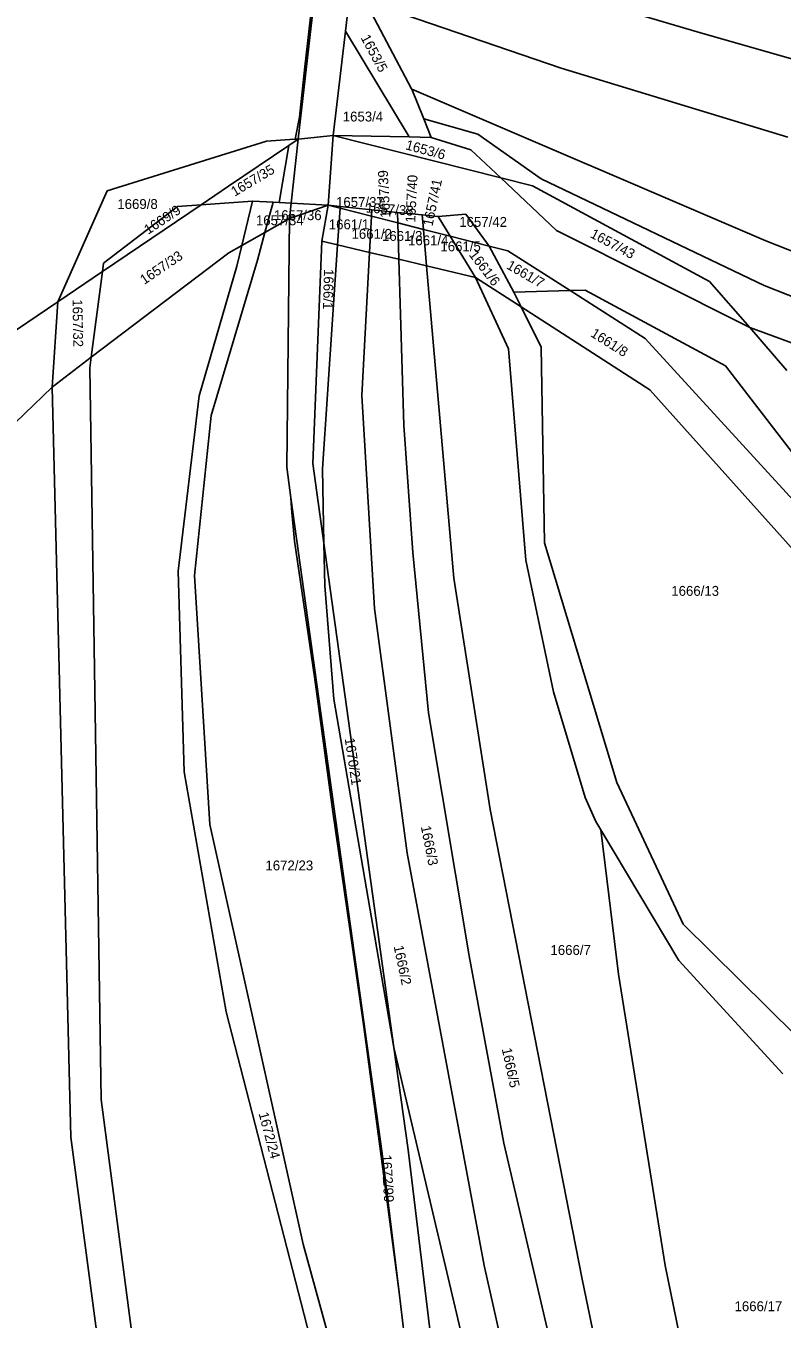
# Model space of a CAD drawing. Extents: x -563148 to -561712, y -1182311 to -1179502.
# Drawn here: x -562402.8 to -562287.9, y -1181888.8 to -1181692.5 of the extents above; entities that cross this region are included whole.
import ezdxf

# ---------------------------------------------------------------- set-up
doc = ezdxf.new("R2010")
doc.units = 0
for name, color, linetype in [('Vrstva 55', 7, 'Continuous'), ('Vrstva 56', 7, 'Continuous'), ('Vrstva 57', 7, 'Continuous')]:
    doc.layers.add(name, color=color, linetype=linetype)

msp = doc.modelspace()

# ---------------------------------------------------------------- linework, layer by layer
at = {"layer": 'Vrstva 55'}
for p, q in [((-562353.53, -1181639.72), (-562361.42, -1181709.69)), ((-562352.46, -1181678.14), (-562300, -1181693.68)), ((-562359.06, -1181686.55), (-562360.44, -1181698.73)), ((-562354.26, -1181693.32), (-562353.26, -1181684.94)), ((-562351.25, -1181688.74), (-562344.21, -1181702.05)), ((-562351.25, -1181688.74), (-562321.53, -1181698.95)), ((-562356.13, -1181709.15), (-562354.26, -1181693.32)), ((-562354.26, -1181693.32), (-562344.6, -1181709.34)), ((-562300, -1181693.68), (-562248.69, -1181708.34)), ((-562360.44, -1181698.73), (-562361.25, -1181706.38)), ((-562287.09, -1181709.38), (-562321.53, -1181698.95)), ((-562344.21, -1181702.05), (-562344.18, -1181702.13)), ((-562344.18, -1181702.13), (-562342.37, -1181706.61)), ((-562344.18, -1181702.13), (-562290.42, -1181725.11)), ((-562361.25, -1181706.38), (-562361.92, -1181709.72)), ((-562342.37, -1181706.61), (-562341.22, -1181709.47)), ((-562342.37, -1181706.61), (-562334.18, -1181708.95)), ((-562366.23, -1181709.99), (-562390.45, -1181717.55)), ((-562362.72, -1181709.77), (-562366.23, -1181709.99)), ((-562362.87, -1181710.67), (-562361.42, -1181709.69)), ((-562361.92, -1181709.72), (-562362.72, -1181709.77)), ((-562361.42, -1181709.69), (-562361.92, -1181709.72)), ((-562361.42, -1181709.69), (-562356.13, -1181709.15)), ((-562356.13, -1181709.15), (-562344.6, -1181709.34)), ((-562356.13, -1181709.15), (-562330.66, -1181715.59)), ((-562344.6, -1181709.34), (-562341.22, -1181709.47)), ((-562341.22, -1181709.47), (-562335.22, -1181711.3)), ((-562324.54, -1181715.73), (-562334.18, -1181708.95)), ((-562372.02, -1181716.86), (-562362.87, -1181710.67)), ((-562364.32, -1181719.33), (-562362.87, -1181710.67)), ((-562335.22, -1181711.3), (-562330.66, -1181715.59)), ((-562330.66, -1181715.59), (-562325.87, -1181716.8)), ((-562330.66, -1181715.59), (-562322.2, -1181723.55)), ((-562290.68, -1181731.89), (-562324.54, -1181715.73)), ((-562390.45, -1181717.55), (-562397.96, -1181734.41)), ((-562376.15, -1181719.65), (-562372.02, -1181716.86)), ((-562298.96, -1181731.29), (-562325.87, -1181716.8)), ((-562391.15, -1181729.8), (-562376.15, -1181719.65)), ((-562379.77, -1181719.9), (-562390.98, -1181728.5)), ((-562379.77, -1181719.9), (-562376.15, -1181719.65)), ((-562376.15, -1181719.65), (-562368.38, -1181719.12)), ((-562369.99, -1181725.83), (-562368.38, -1181719.12)), ((-562368.38, -1181719.12), (-562368.31, -1181719.12)), ((-562368.31, -1181719.12), (-562365.26, -1181719.28)), ((-562366.5, -1181723.86), (-562365.26, -1181719.28)), ((-562365.26, -1181719.28), (-562364.32, -1181719.33)), ((-562364.32, -1181719.33), (-562362.52, -1181719.42)), ((-562356.88, -1181719.72), (-562362.78, -1181721.75)), ((-562362.52, -1181719.42), (-562356.88, -1181719.72)), ((-562357.84, -1181725.18), (-562356.88, -1181719.72)), ((-562356.88, -1181719.72), (-562355.06, -1181719.91)), ((-562356.88, -1181719.72), (-562355.08, -1181720.18)), ((-562355.08, -1181720.18), (-562355.06, -1181719.91)), ((-562355.06, -1181719.91), (-562350.26, -1181720.41)), ((-562366.5, -1181723.86), (-562362.78, -1181721.75)), ((-562363.17, -1181759.5), (-562362.78, -1181721.75)), ((-562355.45, -1181725.74), (-562355.08, -1181720.18)), ((-562355.08, -1181720.18), (-562350.31, -1181721.39)), ((-562350.61, -1181726.88), (-562350.31, -1181721.39)), ((-562350.31, -1181721.39), (-562350.26, -1181720.41)), ((-562350.31, -1181721.39), (-562346.32, -1181722.41)), ((-562350.26, -1181720.41), (-562346.37, -1181720.81)), ((-562346.37, -1181720.81), (-562346.32, -1181722.41)), ((-562346.37, -1181720.81), (-562342.62, -1181721.2)), ((-562342.62, -1181721.2), (-562342.43, -1181723.4)), ((-562342.62, -1181721.2), (-562340.17, -1181721.46)), ((-562336, -1181721.07), (-562340.17, -1181721.46)), ((-562340.17, -1181721.46), (-562338.34, -1181724.44)), ((-562336, -1181721.07), (-562332.44, -1181725.94)), ((-562369.99, -1181725.83), (-562366.5, -1181723.86)), ((-562367.64, -1181728.05), (-562366.5, -1181723.86)), ((-562346.32, -1181722.41), (-562346.15, -1181727.94)), ((-562346.32, -1181722.41), (-562342.43, -1181723.4)), ((-562342.43, -1181723.4), (-562341.95, -1181728.93)), ((-562342.43, -1181723.4), (-562338.34, -1181724.44)), ((-562322.2, -1181723.55), (-562292.88, -1181738.3)), ((-562371.95, -1181726.94), (-562369.99, -1181725.83)), ((-562370.75, -1181728.97), (-562369.99, -1181725.83)), ((-562359.21, -1181758.95), (-562357.84, -1181725.18)), ((-562357.84, -1181725.18), (-562355.45, -1181725.74)), ((-562357.75, -1181759.73), (-562355.45, -1181725.74)), ((-562355.45, -1181725.74), (-562350.61, -1181726.88)), ((-562338.34, -1181724.44), (-562334.52, -1181730.68)), ((-562338.34, -1181724.44), (-562332.44, -1181725.94)), ((-562251.08, -1181740.75), (-562290.42, -1181725.11)), ((-562392.85, -1181742.79), (-562371.95, -1181726.94)), ((-562351.79, -1181748.62), (-562350.61, -1181726.88)), ((-562350.61, -1181726.88), (-562346.15, -1181727.94)), ((-562332.44, -1181725.94), (-562328.71, -1181732.93)), ((-562332.44, -1181725.94), (-562329.62, -1181726.66)), ((-562329.62, -1181726.66), (-562320.13, -1181732.69)), ((-562397.96, -1181734.41), (-562391.15, -1181729.8)), ((-562392.85, -1181742.79), (-562391.15, -1181729.8)), ((-562391.15, -1181729.8), (-562390.98, -1181728.5)), ((-562370.75, -1181728.97), (-562376.47, -1181748.67)), ((-562367.64, -1181728.05), (-562374.64, -1181751.65)), ((-562346.15, -1181727.94), (-562345.38, -1181753.09)), ((-562346.15, -1181727.94), (-562341.95, -1181728.93)), ((-562341.95, -1181728.93), (-562337.82, -1181776.34)), ((-562341.95, -1181728.93), (-562334.52, -1181730.68)), ((-562334.52, -1181730.68), (-562329.49, -1181741.53)), ((-562334.52, -1181730.68), (-562327.6, -1181735.14)), ((-562298.96, -1181731.29), (-562292.88, -1181738.3)), ((-562328.71, -1181732.93), (-562320.13, -1181732.69)), ((-562328.71, -1181732.93), (-562327.6, -1181735.14)), ((-562320.13, -1181732.69), (-562317.84, -1181732.63)), ((-562320.13, -1181732.69), (-562308.73, -1181739.94)), ((-562317.84, -1181732.63), (-562296.54, -1181744.09)), ((-562255.51, -1181745.96), (-562290.68, -1181731.89)), ((-562407.4, -1181740.8), (-562397.96, -1181734.41)), ((-562397.96, -1181734.41), (-562398.82, -1181747.32)), ((-562327.6, -1181735.14), (-562308.02, -1181747.77)), ((-562327.6, -1181735.14), (-562324.54, -1181741.27)), ((-562292.88, -1181738.3), (-562255.51, -1181751.96)), ((-562292.88, -1181738.3), (-562287.23, -1181744.81)), ((-562329.49, -1181741.53), (-562326.89, -1181773.59)), ((-562324.54, -1181741.27), (-562324.02, -1181770.98)), ((-562308.73, -1181739.94), (-562275.46, -1181776.35)), ((-562398.82, -1181747.32), (-562392.85, -1181742.79)), ((-562393.06, -1181744.4), (-562392.85, -1181742.79)), ((-562393.06, -1181744.4), (-562391.36, -1181855.43)), ((-562296.54, -1181744.09), (-562274.55, -1181772.73)), ((-562398.82, -1181747.32), (-562422.96, -1181770.64)), ((-562398.82, -1181747.32), (-562395.94, -1181861.16)), ((-562376.47, -1181748.67), (-562379.68, -1181775.25)), ((-562349.85, -1181780.92), (-562351.79, -1181748.62)), ((-562308.02, -1181747.77), (-562276.99, -1181782.4)), ((-562374.64, -1181751.65), (-562377.16, -1181775.93)), ((-562344.01, -1181772.45), (-562345.38, -1181753.09)), ((-562357.53, -1181771), (-562359.21, -1181758.95)), ((-562362.53, -1181764.12), (-562363.17, -1181759.5)), ((-562357.53, -1181771), (-562357.75, -1181759.73)), ((-562348.7, -1181863.65), (-562362.53, -1181764.12)), ((-562346.89, -1181847.56), (-562357.53, -1181771)), ((-562357.41, -1181777.49), (-562357.53, -1181771)), ((-562324.02, -1181770.98), (-562313.04, -1181807.32)), ((-562341.66, -1181796.78), (-562344.01, -1181772.45)), ((-562326.89, -1181773.59), (-562322.65, -1181793.58)), ((-562379.68, -1181775.25), (-562378.76, -1181805.72)), ((-562377.16, -1181775.93), (-562374.87, -1181813.74)), ((-562332.27, -1181811.45), (-562337.82, -1181776.34)), ((-562356.03, -1181794.67), (-562357.41, -1181777.49)), ((-562344.87, -1181818.09), (-562349.85, -1181780.92)), ((-562322.65, -1181793.58), (-562317.84, -1181809.61)), ((-562356.03, -1181794.67), (-562346.89, -1181847.56)), ((-562341.66, -1181796.78), (-562335.48, -1181833.67)), ((-562378.76, -1181805.72), (-562372.35, -1181842.15)), ((-562313.04, -1181807.32), (-562302.97, -1181828.86)), ((-562317.84, -1181809.61), (-562316.24, -1181813.28)), ((-562332.27, -1181811.45), (-562318.3, -1181882.7)), ((-562374.87, -1181813.74), (-562360.67, -1181877.43)), ((-562316.24, -1181813.28), (-562315.49, -1181814.54)), ((-562315.49, -1181814.54), (-562312.8, -1181836.42)), ((-562315.49, -1181814.54), (-562303.64, -1181834.36)), ((-562344.87, -1181818.09), (-562333.19, -1181880.63)), ((-562302.97, -1181828.86), (-562285.86, -1181845.74)), ((-562335.48, -1181833.67), (-562330.21, -1181862.08)), ((-562303.64, -1181834.36), (-562287.83, -1181851.54)), ((-562312.8, -1181836.42), (-562305.7, -1181880.63)), ((-562372.35, -1181842.15), (-562346.55, -1181942.6)), ((-562346.89, -1181847.56), (-562324.43, -1181942.99)), ((-562344.73, -1181863.1), (-562346.89, -1181847.56)), ((-562391.36, -1181855.43), (-562383.8, -1181913.17)), ((-562395.94, -1181861.16), (-562388.61, -1181916.83)), ((-562344.73, -1181863.1), (-562334.86, -1181945.16)), ((-562330.21, -1181862.08), (-562311.94, -1181940.39)), ((-562346.12, -1181884.73), (-562348.7, -1181863.65)), ((-562360.67, -1181877.43), (-562343.26, -1181940.43)), ((-562333.19, -1181880.63), (-562319.33, -1181941.93)), ((-562294.23, -1181936.71), (-562305.7, -1181880.63)), ((-562318.3, -1181882.7), (-562306.8, -1181939.32)), ((-562338.63, -1181945.94), (-562346.12, -1181884.73))]:
    msp.add_line(p, q, dxfattribs=at)
msp.add_lwpolyline([(-562362.53, -1181764.12), (-562362.44, -1181765.77), (-562362, -1181770.7), (-562358.94, -1181791.3), (-562356.17, -1181811.78), (-562353.56, -1181829.89), (-562351.48, -1181844.4), (-562348.95, -1181863.27), (-562346.12, -1181884.73)], dxfattribs=at)
at = {"layer": 'Vrstva 56'}
for p, q in [((-562362.52, -1181719.42), (-562361.42, -1181709.69)), ((-562356.13, -1181709.15), (-562356.88, -1181719.72)), ((-562362.78, -1181721.75), (-562362.52, -1181719.42))]:
    msp.add_line(p, q, dxfattribs=at)

# ---------------------------------------------------------------- texts
at = {"layer": 'Vrstva 57'}
for s, rotation, p in [('1653/5', 298.2374, (-562351.99, -1181694.31)), ('1653/6', 344.6667, (-562345.24, -1181711.22)), ('1657/35', 30.8394, (-562371.08, -1181718.45)), ('1657/39', 93.1555, (-562347.44, -1181721.61)), ('1657/40', 87.1266, (-562343.67, -1181722.4)), ('1657/41', 78.2995, (-562341.05, -1181723.01)), ('1669/9', 33.4078, (-562384.22, -1181724.23)), ('1657/38', 355.9144, (-562351.21, -1181720.82)), ('1657/43', 331.9727, (-562317.22, -1181724.53)), ('1657/33', 34.1067, (-562384.82, -1181731.84)), ('1661/6', 307.4545, (-562335.58, -1181727.27)), ('1666/1', 268.5343, (-562357.52, -1181729.4)), ('1661/7', 330.0927, (-562329.93, -1181729.27)), ('1657/32', 271.0007, (-562395.71, -1181734.02)), ('1661/8', 327.7032, (-562317.16, -1181739.55)), ('1670/21', 278.5091, (-562354.38, -1181800.68)), ('1666/3', 281.231, (-562342.82, -1181814.04)), ('1666/2', 281.9235, (-562346.95, -1181832.21)), ('1666/5', 282.2193, (-562330.53, -1181847.78)), ('1672/24', 284.9394, (-562367.46, -1181857.58)), ('1672/99', 273.2425, (-562348.79, -1181863.86))]:
    msp.add_text(s, height=1.5, rotation=rotation, dxfattribs=at).set_placement(p)
for s, p in [('1653/4', (-562354.67, -1181707.02)), ('1669/8', (-562388.9, -1181720.3)), ('1657/37', (-562355.69, -1181720)), ('1657/34', (-562367.86, -1181722.77)), ('1657/36', (-562365.13, -1181721.99)), ('1661/1', (-562356.79, -1181723.38)), ('1657/42', (-562336.98, -1181723.01)), ('1661/2', (-562353.34, -1181724.83)), ('1661/3', (-562348.71, -1181725.14)), ('1661/4', (-562344.76, -1181725.81)), ('1661/5', (-562339.84, -1181726.72)), ('1666/13', (-562304.78, -1181779.01)), ('1672/23', (-562366.41, -1181820.68)), ('1666/7', (-562323.13, -1181833.51)), ('1666/17', (-562295.18, -1181887.58))]:
    msp.add_text(s, height=1.5, dxfattribs=at).set_placement(p)

doc.saveas('drawing.dxf')
